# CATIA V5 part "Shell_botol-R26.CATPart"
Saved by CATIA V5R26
Part number: botol
Definition: botol
Nomenclature: botol
Source: Unknown
Bounding box of the stored display mesh (mm): x -28.508 to 26.509, y -28.514 to 28.514, z 0 to 220
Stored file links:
  C:\Users\ina\Downloads\Shell-裏技\Shell_botol.CATPart
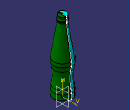
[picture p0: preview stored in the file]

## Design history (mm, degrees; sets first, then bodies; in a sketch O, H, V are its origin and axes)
Body1 (main body)
Body2
  Body3
    Sketch1 on yz-plane, origin (0, 0, 0), H (0, 0, 1), V (0, 1, 0)
      line L1 (0, 0) -> (0, 21)
      line L2 (7, 28) -> (23.0098, 28)
      line L3 (80.644, 25.587) -> (94.232, 27.9829)
      line L4 (105.7849, 28.0838) -> (201.3811, 12.9428)
      line L5 (203.2, 13.2799) -> (204, 13.7418)
      line L6 (207.9619, 14.1932) -> (213.5, 12.5)
      point P1 (213.5, 12.5)
      line L7 (213.5, 12.5) -> (220, 12.5)
      line L8 (220, 12.5) -> (220, 0)
      point P3 (220, 0)
      arc A1 centre (60.2576, 141.204) radius 117.4005 from (80.644, 25.587) to (34.1352, 26.7466) cw
      arc A2 centre (206.5, 9.4117) radius 5 from (204, 13.7418) to (207.9619, 14.1932) cw
      arc A3 centre (201.8146, 15.6796) radius 2.7709 from (203.2, 13.2799) to (201.3811, 12.9428) cw
      arc A4 centre (7, 21) radius 7 from (7, 28) to (0, 21) ccw
      arc A5 centre (100.3097, -6.4853) radius 35 from (94.232, 27.9829) to (105.7849, 28.0838) cw
      arc A6 centre (23.0098, -22) radius 50 from (34.1352, 26.7466) to (23.0098, 28) ccw
      axis line L9 (-64.4672, 0) -> (249.2484, 0)
      point P16 (-64.4672, 0)
      construction line L10 (29.149, 28) -> (56.1496, 21.268)
      point P18 (29.149, 28)
      point P19 (56.1496, 21.268)
      point P20 (100, 29)
      construction line L11 (100, 29) -> (100, 38.1548)
      construction line L12 (206.5, 9.4117) -> (206.5, 18.8124)
      radius A2 = 5
      radius A3 = 2.7709
      radius A4 = 7
      radius A5 = 35
      radius A6 = 50
      distance L9 L2 = 28
      distance P18 L1 = 29.149
      angle L10 L2 = 14
      distance L11 L1 = 100
      angle L4 L11 = 99
      angle L3 L11 = 100
      distance P20 L9 = 29
      distance L8 L1 = 220
      distance L9 L7 = 12.5
      distance P1 L8 = 6.5
      angle L9 L6 = 17
      distance L12 L8 = 13.5
      angle L5 L12 = 120
      vertical: L1 V, L8 V, L11 V, L12 V
      horizontal: L2 H, L7 H, L9 H
      coincidence: P3 H, P16 L3, P16 H, P18 A1, P18 L2, P19 L3, P20 L3, P20 L4
      tangency: A1 L3, A2 L5, A2 L6, A3 L5, A3 L4, A4 L2, A4 L1, A5 L3, A5 L4, A6 A1, A6 L2, L10 A6
    Shaft1: profile Sketch1, axis Sketch1.L9, angle 360
    Shell1: ExtOffset 0, IntOffset 2
  Assemble1: tool Body3
  Trim1: faces to remove face of Shaft1 from Sketch1.L4
Body4
  Solid1: linked copy from another document
  Split1: SplitPlane yz-plane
